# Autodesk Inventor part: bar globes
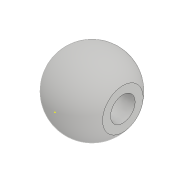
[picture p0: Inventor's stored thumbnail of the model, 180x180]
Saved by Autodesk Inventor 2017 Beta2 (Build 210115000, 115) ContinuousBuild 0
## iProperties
Created: 2016-03
Part Number: bar globes
Material: Generic
Document SubType Name: Modeling
Designer: Sandeep
Density: 1 g/cm^3
Appearance: Default
Author: Sandeep
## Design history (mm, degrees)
sketch "Sketch1"
  geometry: L1 (0, 12)-(0, 0); A1 r 6 centre (0, 6) between (0, 12) and (0, 0)
  constraints: 2 end point, 2 point on circle, 1 centre point, 1 midpoint, 1 vertical
revolve "Revolution1" sketch "Sketch1" stored, may be unused: angle "d1" = 90 deg
sketch "Sketch2"
  geometry: 1 further point
sketch "Sketch3"
  geometry: 1 further point
sketch "Sketch4"
  geometry: 1 further point
sketch "Sketch5"
  geometry: L1 (5.014, 9.295)-(5.014, 2.705); A1 r 6 centre (0, 6) between (0, 0) and (5.014, 9.295) reference; A2 r 6 centre (0, 6) between (0, 0) and (5.014, 2.705) reference; 2 further points
  constraints: 2 end point, 2 point on circle, 1 vertical, 1 vertical alignment
extrude "Extrusion1" cut sketch "Sketch5" stored distance "d2" = 10; taper "d3" = 0 deg
sketch "Sketch6"
  geometry: L1 (5.65, 4.164)-(5.65, -4.091); A1 r 6 centre (0, 0) between (-5.014, -3.295) and (-5.014, 3.295) reference; 1 further point
  constraints: 2 end point, 1 vertical
extrude "Extrusion2" cut sketch "Sketch6" distance "d5" = 15.75; taper "d6" = 0 deg
sketch "Sketch7"
  geometry: L1 (-5.65, 3.981)-(-5.65, 8.019) reference; L2 (-5.65, 6)-(5.014, 6); L3 (-4.986, 8)-(5.014, 8); L4 (5.014, 8)-(5.014, 6); L5 (5.014, 9.295)-(5.014, 2.705) reference; L6 (-5.65, 7.336)-(-5.65, 6); L7 (-4.986, 8)-(-5.65, 7.336); 3 further points
  constraints: 10 end point, 2 collinear, 2 horizontal, 2 midpoint, 2 point on line
  dimensions: "d16" = 4 diameter of L3 L2; "d17" = 10 distance of L3.end L3.start; "d19" = 45 deg angle of L7 L3
revolve "Revolution2" sketch "Sketch7" stored, may be unused: angle "d18" = 90 deg
body "Solid1"
other parameters: "d4" = 15.75
